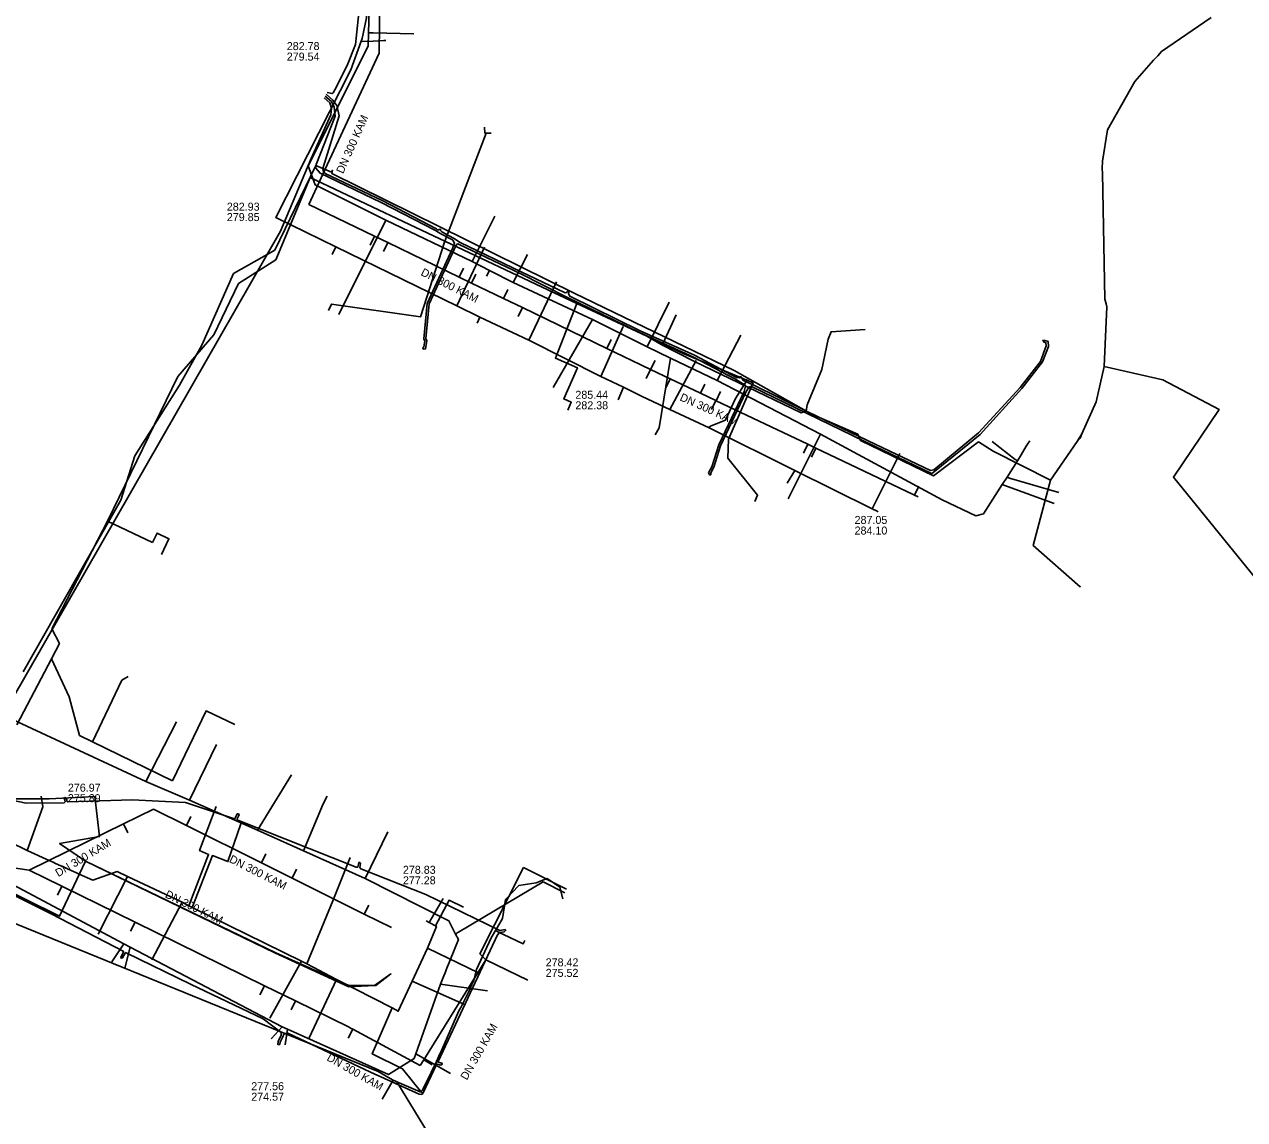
# Model space of a CAD drawing. Extents: x -600309 to -598967, y -1161267 to -1160292.
# Drawn here: x -599921.2 to -599799.2, y -1160753.6 to -1160644.2 of the extents above; entities that cross this region are included whole.
import ezdxf

# ---------------------------------------------------------------- set-up
doc = ezdxf.new("R2010")
doc.units = 0
for name, color, linetype in [('Vrstva 12', 7, 'Continuous'), ('Vrstva 13', 7, 'Continuous'), ('Vrstva 19', 7, 'Continuous'), ('Vrstva 42', 7, 'Continuous'), ('Vrstva 5', 7, 'Continuous'), ('Vrstva 55', 7, 'Continuous'), ('Vrstva 9', 7, 'Continuous')]:
    doc.layers.add(name, color=color, linetype=linetype)

msp = doc.modelspace()

# ---------------------------------------------------------------- linework, layer by layer
at = {"layer": 'Vrstva 12'}
for points in [[(-599875.17, -1160654.44), (-599875.15, -1160655.02), (-599875.03, -1160655.02)], [(-599875.03, -1160655.02), (-599879.14, -1160665.83)], [(-599875.03, -1160655.02), (-599874.53, -1160655.03)], [(-599912.88, -1160693.81), (-599905.85, -1160679.36), (-599902.23, -1160675.17), (-599899.77, -1160670.05), (-599896.05, -1160667.69), (-599892.6, -1160659.46), (-599880.23, -1160665.32)], [(-599880.23, -1160665.32), (-599879.14, -1160665.83)], [(-599890.78, -1160672.75), (-599890.48, -1160672.11), (-599881.58, -1160673.38), (-599879.14, -1160665.83)], [(-599879.14, -1160665.83), (-599868.85, -1160670.69)], [(-599868.85, -1160670.69), (-599865.96, -1160672.05)], [(-599865.96, -1160672.05), (-599868.1, -1160677.51), (-599865.9, -1160678.47), (-599867.26, -1160681.59), (-599866.52, -1160681.92), (-599866.86, -1160682.71)], [(-599865.96, -1160672.05), (-599858.96, -1160675.31)], [(-599857.37, -1160676.07), (-599856.01, -1160673.18)], [(-599837.12, -1160674.65), (-599840.54, -1160674.87), (-599840.84, -1160675.61), (-599841.47, -1160678.65), (-599842.93, -1160682.16), (-599843.04, -1160682.81), (-599843.53, -1160682.99), (-599854.18, -1160677.84), (-599857.51, -1160676.16), (-599858.96, -1160675.31)], [(-599858.96, -1160675.31), (-599857.37, -1160676.07)], [(-599857.37, -1160676.07), (-599855.32, -1160677.06), (-599848.33, -1160679.98), (-599850.79, -1160685.62), (-599850.86, -1160687.52), (-599847.88, -1160691.22), (-599848.17, -1160691.85)], [(-599918.44, -1160704.56), (-599912.88, -1160693.81)], [(-599912.88, -1160693.81), (-599908.36, -1160695.95)], [(-599908.36, -1160695.95), (-599907.91, -1160695), (-599906.73, -1160695.56), (-599907.49, -1160697.14)], [(-599918.46, -1160707.55), (-599917.67, -1160706.04), (-599918.44, -1160704.56)], [(-599921.92, -1160714.16), (-599918.46, -1160707.55)], [(-599918.46, -1160707.55), (-599916.7, -1160711.37), (-599915.67, -1160715.21), (-599914.36, -1160715.85)], [(-599914.36, -1160715.85), (-599911.44, -1160709.71), (-599910.82, -1160709.34)], [(-599906.36, -1160719.75), (-599903.01, -1160712.77), (-599900.13, -1160714.12)], [(-599914.36, -1160715.85), (-599906.36, -1160719.75)], [(-599874.09, -1160734.73), (-599874.02, -1160734.62), (-599873.4, -1160733.52), (-599873.08, -1160731.63), (-599871.75, -1160730.23), (-599870.02, -1160729.96), (-599868.91, -1160729.53), (-599867.67, -1160730.39), (-599867.36, -1160731.55)], [(-599885.82, -1160748.81), (-599923.71, -1160733.38), (-599927.07, -1160740.62)], [(-599876.26, -1160739.7), (-599876, -1160738.62), (-599874.52, -1160735.44), (-599874.09, -1160734.73)], [(-599874.09, -1160734.73), (-599873.65, -1160734.94), (-599873.29, -1160735.11)], [(-599873.29, -1160735.11), (-599871.33, -1160736.06), (-599871.16, -1160735.7)], [(-599881.06, -1160750), (-599879.98, -1160747.8), (-599879.62, -1160746.99), (-599879.46, -1160746.64), (-599877.76, -1160742.76), (-599877.55, -1160742.41), (-599877.13, -1160741.53), (-599876.72, -1160740.76), (-599876.44, -1160740.12), (-599876.26, -1160739.7)], [(-599884.63, -1160749.51), (-599885.82, -1160748.81)], [(-599885.41, -1160751.56), (-599884.31, -1160749.69), (-599884.16, -1160749.75)], [(-599884.31, -1160749.69), (-599884.63, -1160749.51)], [(-599884.16, -1160749.75), (-599883.96, -1160749.84)], [(-599883.96, -1160749.84), (-599881.6, -1160750.84), (-599881.41, -1160750.7), (-599881.06, -1160750)], [(-599877.06, -1160759.02), (-599877.2, -1160759.34), (-599878.56, -1160758.7), (-599883.96, -1160749.84)]]:
    msp.add_lwpolyline(points, dxfattribs=at)
at = {"layer": 'Vrstva 13'}
for p, q in [((-599885.05, -1160663.71), (-599889.76, -1160673.14)), ((-599876.42, -1160667.86), (-599874.16, -1160663.32)), ((-599872.31, -1160669.94), (-599870.9, -1160667.16)), ((-599874.68, -1160668.76), (-599874.98, -1160669.32)), ((-599858.93, -1160676.38), (-599856.72, -1160671.93)), ((-599864.38, -1160673.64), (-599868.32, -1160680.44)), ((-599851.94, -1160679.73), (-599849.56, -1160675.21)), ((-599841.6, -1160685.11), (-599844.82, -1160691.56)), ((-599821.03, -1160686.32), (-599820.9, -1160686.11)), ((-599820.9, -1160686.11), (-599820.68, -1160685.76)), ((-599909.03, -1160719.82), (-599905.97, -1160713.85)), ((-599904.66, -1160721.7), (-599901.96, -1160716.12)), ((-599897.88, -1160724.7), (-599894.49, -1160719.15)), ((-599887.11, -1160729.51), (-599884.86, -1160724.84)), ((-599911.25, -1160736.05), (-599912.44, -1160737.85)), ((-599910.61, -1160736.39), (-599911.15, -1160738.48)), ((-599879.59, -1160740.07), (-599874.9, -1160740.75)), ((-599895.41, -1160744.33), (-599896.5, -1160745.56)), ((-599894.89, -1160744.59), (-599895.11, -1160746.14)), ((-599882.04, -1160747.04), (-599878.57, -1160749.01))]:
    msp.add_line(p, q, dxfattribs=at)
for points in [[(-599888.79, -1160625.29), (-599886.65, -1160625.29), (-599886.25, -1160625.7), (-599886.25, -1160626.89), (-599886.25, -1160627.2), (-599886.79, -1160645), (-599886.82, -1160646.32), (-599892.8, -1160658.29), (-599892.12, -1160660.2), (-599885.05, -1160663.71), (-599876.42, -1160667.86), (-599874.68, -1160668.76), (-599872.31, -1160669.94), (-599864.38, -1160673.64), (-599858.93, -1160676.38), (-599856.6, -1160677.51), (-599851.94, -1160679.73), (-599841.6, -1160685.11), (-599829.45, -1160691.68)], [(-599886.79, -1160645), (-599886.31, -1160645), (-599882.26, -1160645.09)], [(-599856.6, -1160677.51), (-599857.73, -1160684.47), (-599858.12, -1160685.16)], [(-599829.45, -1160691.68), (-599826.08, -1160693.27), (-599825.32, -1160693.08), (-599823.43, -1160690.14), (-599822.95, -1160689.39), (-599821.91, -1160687.76), (-599821.55, -1160687.16), (-599821.03, -1160686.32)], [(-599821.91, -1160687.76), (-599822.13, -1160687.63), (-599824.43, -1160685.84)], [(-599822.95, -1160689.39), (-599822.7, -1160689.49), (-599817.76, -1160690.93)], [(-599823.43, -1160690.14), (-599823.18, -1160690.25), (-599818.23, -1160692.04)], [(-599927.13, -1160711.44), (-599909.03, -1160719.82), (-599904.66, -1160721.7), (-599897.88, -1160724.7), (-599893.27, -1160726.74), (-599887.11, -1160729.51), (-599878.74, -1160733.74), (-599878.18, -1160734.89), (-599878.09, -1160735.07), (-599877.79, -1160735.63), (-599879.01, -1160738.64), (-599879.13, -1160738.94)], [(-599893.27, -1160726.74), (-599891.3, -1160722.04), (-599890.9, -1160721.3)], [(-599879.13, -1160738.94), (-599879.25, -1160739.26), (-599879.59, -1160740.07), (-599882.04, -1160747.04), (-599882.22, -1160747.5), (-599884.79, -1160749.11), (-599894.89, -1160744.59), (-599895.41, -1160744.33), (-599910.61, -1160736.39), (-599911.25, -1160736.05), (-599932.41, -1160724.79), (-599932.66, -1160724.68)], [(-599878.09, -1160735.07), (-599877.99, -1160735.01), (-599877.91, -1160734.96), (-599877.77, -1160734.88), (-599869.33, -1160729.84)], [(-599869.33, -1160729.85), (-599867.17, -1160730.94)]]:
    msp.add_lwpolyline(points, dxfattribs=at)
at = {"layer": 'Vrstva 19'}
for points in [[(-599887.1, -1160629.56), (-599887.02, -1160632.18), (-599887.06, -1160632.95), (-599887.11, -1160633.81), (-599886.99, -1160641.11), (-599886.97, -1160642.03), (-599886.97, -1160643.51), (-599887.41, -1160645.57), (-599887.51, -1160645.84), (-599888.55, -1160648.69), (-599896.05, -1160663.45), (-599890.03, -1160666.37), (-599877.94, -1160672.29), (-599875.65, -1160673.42), (-599870.75, -1160675.7), (-599863.55, -1160679.34), (-599861.29, -1160680.42), (-599859.43, -1160681.33), (-599856.65, -1160682.64), (-599852.72, -1160684.49), (-599844.17, -1160688.74), (-599836.42, -1160692.57), (-599835.92, -1160692.82), (-599835.83, -1160692.86)], [(-599887.51, -1160645.84), (-599886.84, -1160645.87), (-599885.24, -1160645.77), (-599885.05, -1160645.76)], [(-599890.03, -1160666.37), (-599890.41, -1160667.14)], [(-599877.94, -1160672.29), (-599875.2, -1160666.43)], [(-599870.75, -1160675.7), (-599868, -1160669.88)], [(-599875.65, -1160673.42), (-599875.92, -1160674)], [(-599863.55, -1160679.34), (-599861.34, -1160674.36)], [(-599856.65, -1160682.64), (-599854.01, -1160677.74)], [(-599852.72, -1160684.49), (-599852.7, -1160684.37), (-599852.54, -1160684.26), (-599851.11, -1160683.72), (-599850.1, -1160681.55), (-599848.91, -1160679.64)], [(-599861.29, -1160680.42), (-599861.84, -1160681.68)], [(-599836.42, -1160692.57), (-599833.67, -1160687.05)], [(-599844.17, -1160688.74), (-599844.94, -1160690)], [(-599920.91, -1160726.73), (-599919.34, -1160722.37), (-599919.49, -1160721.3)], [(-599881, -1160733.76), (-599880.72, -1160733.91), (-599880.08, -1160734.26), (-599879.99, -1160734.31), (-599880.87, -1160736.47), (-599882.41, -1160739.77), (-599883.81, -1160742.78), (-599884.42, -1160742.46), (-599889.97, -1160739.62), (-599892.95, -1160738.04), (-599893.49, -1160737.78), (-599904.4, -1160732.41), (-599904.73, -1160732.24), (-599905.42, -1160731.9), (-599910.87, -1160729.32), (-599911.92, -1160728.82), (-599914.34, -1160729.68), (-599915.71, -1160729.07), (-599916.03, -1160728.92), (-599916.21, -1160728.84), (-599918.12, -1160727.98), (-599918.31, -1160727.9), (-599918.63, -1160727.75), (-599920.91, -1160726.73), (-599930.37, -1160722.08)], [(-599902.01, -1160722.32), (-599903.66, -1160726.73), (-599902.77, -1160727.12), (-599904.73, -1160732.24)], [(-599904.4, -1160732.41), (-599902.38, -1160727.23), (-599900.84, -1160727.82), (-599899.55, -1160724.06)], [(-599892.95, -1160738.04), (-599890.34, -1160731.76), (-599888.6, -1160727.41)], [(-599910.87, -1160729.32), (-599913.81, -1160735.09)], [(-599905.42, -1160731.9), (-599908.43, -1160737.64)], [(-599880.72, -1160733.91), (-599879.33, -1160731.51)], [(-599880.08, -1160734.26), (-599878.72, -1160731.7), (-599877.28, -1160732.37)], [(-599880.87, -1160736.47), (-599875.79, -1160738.94)], [(-599893.49, -1160737.78), (-599896.64, -1160743.47)], [(-599889.97, -1160739.62), (-599892.72, -1160745.43)], [(-599882.41, -1160739.77), (-599877.2, -1160742.12)], [(-599884.42, -1160742.46), (-599886.4, -1160747.05), (-599883.37, -1160748.53), (-599881.45, -1160750.94)]]:
    msp.add_lwpolyline(points, dxfattribs=at)
at = {"layer": 'Vrstva 42'}
for points in [[(-599890.92, -1160650.95), (-599890.42, -1160651.06), (-599890.3, -1160650.99), (-599890.16, -1160650.68), (-599888.93, -1160648.25), (-599888.07, -1160646.17), (-599887.75, -1160642.98), (-599888.13, -1160637.44), (-599888.04, -1160634.01), (-599888.04, -1160633.98), (-599888.85, -1160631.51)], [(-599891.2, -1160651.5), (-599890.65, -1160652), (-599890.48, -1160652.51), (-599890.53, -1160653.2), (-599892.5, -1160657.57), (-599895.59, -1160664.83), (-599922.43, -1160711.67)], [(-599891.1, -1160651.31), (-599890.49, -1160651.87), (-599890.2, -1160652.42), (-599890.11, -1160653.32), (-599892, -1160658.14), (-599892.03, -1160658.51), (-599891.62, -1160659.01), (-599885.52, -1160661.94), (-599880.1, -1160664.76), (-599879.55, -1160665.07), (-599878.38, -1160665.69), (-599878.34, -1160665.71), (-599878.19, -1160666.01), (-599878.4, -1160666.56), (-599880.9, -1160672.04), (-599881.25, -1160675.58), (-599881.15, -1160675.8), (-599881.25, -1160676.39), (-599881.36, -1160676.5), (-599881.3, -1160676.6), (-599881.08, -1160676.58), (-599880.95, -1160675.78), (-599881.04, -1160675.55), (-599880.7, -1160672.09), (-599878.22, -1160666.64), (-599877.98, -1160666.16), (-599877.85, -1160666.1), (-599877.72, -1160666.14), (-599871.62, -1160669.04), (-599866.95, -1160671.4), (-599859.69, -1160674.95), (-599854.29, -1160677.4), (-599850.09, -1160679.61), (-599849.12, -1160680.22), (-599849.1, -1160680.32), (-599849.24, -1160680.83), (-599851.77, -1160686.19), (-599852.46, -1160688.36), (-599852.8, -1160688.98), (-599852.7, -1160689.16), (-599852.57, -1160689.16), (-599852.57, -1160688.98), (-599852.27, -1160688.41), (-599851.59, -1160686.27), (-599849.06, -1160680.91), (-599848.75, -1160680.42), (-599848.59, -1160680.33), (-599848.44, -1160680.38), (-599842.93, -1160683.05), (-599836.14, -1160686.34), (-599830.65, -1160688.98), (-599830.46, -1160689.03), (-599830.19, -1160688.84), (-599825.65, -1160685.13), (-599821.48, -1160680.56), (-599819.39, -1160677.89), (-599818.82, -1160676.33), (-599818.85, -1160675.83), (-599819.16, -1160675.73), (-599819.36, -1160675.72), (-599819.23, -1160675.92), (-599819.06, -1160675.97), (-599819.04, -1160676.28), (-599819.62, -1160677.83), (-599821.63, -1160680.43), (-599825.79, -1160684.99), (-599830.28, -1160688.66), (-599830.59, -1160688.73)], [(-599891.01, -1160651.13), (-599890.33, -1160651.74), (-599889.95, -1160652.27), (-599889.71, -1160653.28), (-599891.35, -1160658.55), (-599891.3, -1160658.79), (-599891.1, -1160659.04), (-599885.43, -1160661.76), (-599880, -1160664.59), (-599879.87, -1160664.67), (-599879.71, -1160664.67), (-599879.68, -1160664.63), (-599879.57, -1160664.65), (-599879.54, -1160664.78), (-599879.45, -1160664.9), (-599878.27, -1160665.52), (-599877.61, -1160665.94), (-599871.53, -1160668.87), (-599867.11, -1160670.97), (-599866.96, -1160670.94), (-599866.92, -1160670.86), (-599866.8, -1160670.83), (-599866.74, -1160670.93), (-599866.8, -1160671.07), (-599866.66, -1160671.31), (-599859.61, -1160674.77), (-599854.2, -1160677.22), (-599850, -1160679.44), (-599849.73, -1160679.47), (-599849.67, -1160679.44), (-599849.64, -1160679.37), (-599849.54, -1160679.38), (-599849.35, -1160679.71), (-599848.67, -1160680.06), (-599848.38, -1160680.16), (-599842.85, -1160682.86), (-599836.06, -1160686.15), (-599830.59, -1160688.73)], [(-599929.17, -1160727.76), (-599918.43, -1160733.07), (-599911.29, -1160736.77), (-599911.28, -1160736.88), (-599911.55, -1160737.38), (-599911.5, -1160737.49), (-599911.37, -1160737.46), (-599911.1, -1160736.97), (-599911.07, -1160736.93), (-599910.99, -1160736.96), (-599904.58, -1160740.09), (-599897.32, -1160743.56), (-599895.52, -1160744.91), (-599895.5, -1160745.18), (-599895.81, -1160745.81), (-599895.85, -1160746.1), (-599895.65, -1160746.1), (-599895.62, -1160745.87), (-599895.35, -1160745.33), (-599895.23, -1160745.09), (-599895.07, -1160745.02), (-599894.86, -1160744.99), (-599886.58, -1160748.89), (-599881.72, -1160751.07), (-599881.46, -1160751.11), (-599881.31, -1160750.94), (-599879.99, -1160748.11), (-599879.91, -1160748.07), (-599879.56, -1160748.16), (-599879.41, -1160748.09), (-599879.45, -1160747.98), (-599879.82, -1160747.89), (-599879.82, -1160747.82), (-599873.9, -1160735.15), (-599873.68, -1160734.91), (-599873.22, -1160734.85), (-599873.07, -1160734.73), (-599873.13, -1160734.63), (-599873.64, -1160734.7), (-599881.06, -1160731.11), (-599887.55, -1160728.55), (-599887.66, -1160728.42), (-599887.57, -1160728.02), (-599887.65, -1160727.91), (-599887.76, -1160727.93), (-599887.85, -1160728.37), (-599888, -1160728.37), (-599899.84, -1160723.7), (-599899.94, -1160723.61), (-599899.72, -1160723.14), (-599899.79, -1160723.04), (-599899.91, -1160723.07), (-599900.14, -1160723.56), (-599900.19, -1160723.55), (-599905.06, -1160721.92), (-599910.42, -1160721.65), (-599916.83, -1160721.87), (-599916.92, -1160721.8), (-599916.95, -1160721.64), (-599917, -1160721.48), (-599917.12, -1160721.42), (-599917.2, -1160721.5), (-599917.15, -1160721.69), (-599917.11, -1160721.87), (-599917.21, -1160721.96), (-599921, -1160721.98), (-599923.39, -1160721.5)]]:
    msp.add_lwpolyline(points, dxfattribs=at)
at = {"layer": 'Vrstva 5'}
msp.add_line((-599866.99, -1160730.58), (-599871.27, -1160728.43), dxfattribs=at)
msp.add_lwpolyline([(-599871.27, -1160728.43), (-599875.64, -1160737.04), (-599875.06, -1160737.66)], dxfattribs=at)
at = {"layer": 'Vrstva 55'}
for points in [[(-599802.54, -1160643.45), (-599807.52, -1160646.85), (-599807.89, -1160647.31), (-599808.32, -1160647.73), (-599810.17, -1160649.85), (-599812.92, -1160654.69), (-599813.41, -1160657.83), (-599813.45, -1160658.54), (-599813.42, -1160659.01), (-599813.17, -1160671.57), (-599813.17, -1160671.63), (-599813.03, -1160672.07), (-599812.97, -1160672.38), (-599813.25, -1160678.35), (-599814.04, -1160681.88), (-599815.47, -1160685.08), (-599815.65, -1160685.5), (-599815.93, -1160685.83), (-599818.62, -1160689.72), (-599820.34, -1160696.23), (-599815.64, -1160700.36), (-599820.34, -1160696.23), (-599818.62, -1160689.72), (-599824.33, -1160686.8), (-599825.8, -1160685.89)], [(-599921.3, -1160708.87), (-599911.55, -1160691.72), (-599910.14, -1160687.26), (-599905.68, -1160680.21), (-599903.45, -1160676.22), (-599900.27, -1160669.05), (-599896.16, -1160666.71), (-599892.05, -1160658.25), (-599890.47, -1160658.93), (-599890.39, -1160658.73), (-599890.43, -1160659.04), (-599866.23, -1160671.03), (-599850.24, -1160678.73), (-599842.46, -1160683.11), (-599837.88, -1160685.12)], [(-599825.8, -1160685.89), (-599824.33, -1160686.8), (-599818.62, -1160689.72), (-599815.93, -1160685.83), (-599815.47, -1160685.08), (-599814.04, -1160681.88), (-599813.25, -1160678.35), (-599807.37, -1160679.67), (-599801.75, -1160682.63), (-599806.31, -1160689.4), (-599793.52, -1160705.18)], [(-599837.88, -1160685.12), (-599837.61, -1160685.74), (-599830.3, -1160689.26), (-599825.8, -1160685.89)], [(-599941.38, -1160721.56), (-599917.66, -1160733.3), (-599915.07, -1160727.78), (-599896.16, -1160736.94), (-599888.76, -1160740.35), (-599886.18, -1160740.23), (-599884.54, -1160739.06), (-599886.06, -1160740.23), (-599888.76, -1160740.23), (-599896.05, -1160736.94), (-599915.07, -1160727.78), (-599917.66, -1160726.02), (-599913.66, -1160725.31), (-599914.13, -1160721.32), (-599918.71, -1160721.56), (-599922, -1160721.56)]]:
    msp.add_lwpolyline(points, dxfattribs=at)
at = {"layer": 'Vrstva 9'}
for p, q in [((-599885.73, -1160647.02), (-599885.37, -1160622.05)), ((-599886.6, -1160666.22), (-599886.17, -1160665.32)), ((-599885.29, -1160666.85), (-599884.86, -1160665.95)), ((-599877.29, -1160668.5), (-599877.73, -1160669.4)), ((-599876.04, -1160669.1), (-599876.47, -1160670.01)), ((-599872.84, -1160670.65), (-599873.28, -1160671.55)), ((-599871.83, -1160673.36), (-599871.4, -1160672.46)), ((-599862.52, -1160675.64), (-599862.95, -1160676.54)), ((-599858.14, -1160677.75), (-599858.58, -1160678.65)), ((-599858.14, -1160677.75), (-599858.58, -1160678.65)), ((-599859.02, -1160679.55), (-599858.58, -1160678.65)), ((-599857.05, -1160680.49), (-599856.62, -1160679.58)), ((-599853.17, -1160680.12), (-599853.6, -1160681.02)), ((-599851.6, -1160680.86), (-599852.03, -1160681.76)), ((-599852.49, -1160682.65), (-599852.06, -1160681.75)), ((-599843.31, -1160687.02), (-599842.88, -1160686.12)), ((-599842.5, -1160687.41), (-599842.07, -1160686.5)), ((-599831.78, -1160690.29), (-599832.21, -1160691.19)), ((-599910.84, -1160724.96), (-599911.28, -1160724.07)), ((-599904.55, -1160723.31), (-599904.99, -1160724.21)), ((-599897.05, -1160727.05), (-599897.49, -1160727.95)), ((-599893.97, -1160728.59), (-599894.42, -1160729.48)), ((-599917.88, -1160731.19), (-599917.44, -1160730.29)), ((-599886.76, -1160732.18), (-599887.2, -1160733.08)), ((-599910.56, -1160734.78), (-599910.12, -1160733.89)), ((-599870.87, -1160739.69), (-599875.06, -1160737.66)), ((-599897.63, -1160741.14), (-599897.19, -1160740.24)), ((-599894.52, -1160742.66), (-599894.08, -1160741.76)), ((-599888.83, -1160745.47), (-599888.35, -1160744.59)), ((-599880.41, -1160748.15), (-599881.26, -1160747.63))]:
    msp.add_line(p, q, dxfattribs=at)
for points in [[(-599892.73, -1160662.15), (-599890.9, -1160658.2), (-599885.73, -1160647.02)], [(-599858.58, -1160678.65), (-599860.46, -1160677.74), (-599862.95, -1160676.54), (-599871.4, -1160672.46), (-599873.28, -1160671.55), (-599876.47, -1160670.01), (-599877.73, -1160669.4), (-599884.86, -1160665.95), (-599886.17, -1160665.32), (-599892.73, -1160662.15)], [(-599831.84, -1160691.37), (-599832.21, -1160691.19), (-599832.34, -1160691.13), (-599842.07, -1160686.5), (-599842.88, -1160686.12), (-599852.03, -1160681.76), (-599852.06, -1160681.75), (-599853.6, -1160681.02), (-599856.62, -1160679.58), (-599858.58, -1160678.65)], [(-599908.26, -1160722.58), (-599911.28, -1160724.07), (-599920.7, -1160728.69)], [(-599884.49, -1160734.43), (-599887.2, -1160733.08), (-599894.42, -1160729.48), (-599897.49, -1160727.95), (-599904.99, -1160724.21), (-599908.26, -1160722.58)], [(-599920.7, -1160728.69), (-599925.5, -1160728), (-599930.06, -1160727.34)], [(-599888.73, -1160744.39), (-599894.08, -1160741.76), (-599897.19, -1160740.24), (-599910.12, -1160733.89), (-599917.44, -1160730.29), (-599920.65, -1160728.72), (-599920.7, -1160728.69)], [(-599875.06, -1160737.66), (-599881.26, -1160747.63), (-599881.63, -1160748.22)], [(-599881.63, -1160748.22), (-599888.35, -1160744.59), (-599888.57, -1160744.47), (-599888.73, -1160744.39)]]:
    msp.add_lwpolyline(points, dxfattribs=at)

# ---------------------------------------------------------------- texts
at = {"layer": 'Vrstva 12'}
for s, p in [('282.78', (-599894.95, -1160646.72)), ('279.54', (-599894.95, -1160647.77)), ('282.93', (-599900.94, -1160662.77)), ('279.85', (-599900.94, -1160663.81)), ('285.44', (-599866.1, -1160681.57)), ('282.38', (-599866.1, -1160682.62)), ('287.05', (-599838.19, -1160694.08)), ('284.10', (-599838.19, -1160695.14)), ('276.97', (-599916.83, -1160720.84)), ('275.89', (-599916.83, -1160721.89)), ('278.83', (-599883.34, -1160729.05)), ('277.28', (-599883.34, -1160730.1)), ('278.42', (-599869.07, -1160738.3)), ('275.52', (-599869.07, -1160739.35)), ('277.56', (-599898.5, -1160750.68)), ('274.57', (-599898.5, -1160751.73))]:
    msp.add_text(s, height=0.8, dxfattribs=at).set_placement(p)
for rotation, p in [(65.9474, (-599889.32, -1160659.13)), (333.2323, (-599881.62, -1160669.19)), (335.696, (-599855.73, -1160681.7)), (30.997, (-599917.79, -1160729.39)), (333.0031, (-599900.78, -1160727.84)), (333.8625, (-599907.19, -1160731.37)), (60.1371, (-599876.95, -1160749.73)), (330.3102, (-599891.02, -1160747.65))]:
    msp.add_text('DN 300 KAM', height=0.8, rotation=rotation, dxfattribs=at).set_placement(p)

doc.saveas('drawing.dxf')
